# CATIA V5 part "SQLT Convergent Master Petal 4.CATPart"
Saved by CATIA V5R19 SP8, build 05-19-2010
Part number: SQLT Convergent Master Petal 4
Publications: "Droite.1", "Plan.1", "Plan.2", "Droite.2", "Droite.3", "Plan.3", "Droite.4", "Plan.4", "Plan.5", "Droite.5", "Plan.6", "Plan.7", "Point.4", "Point.5"
Bounding box of the stored display mesh (mm): x -150 to 150, y 530 to 730, z 400 to 600
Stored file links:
  G:\EU_thinkMotion\CFAO_2010\MMS_groupe3\MMS_groupe3\A reprendre\fovide\fovide\SQLT Convergent Master Petal 4.CATPart
  G:\EU_thinkMotion\CFAO_2010\MMS_groupe3\MMS_groupe3\A reprendre\fovide\fovide\fovide.CATProduct
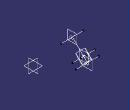
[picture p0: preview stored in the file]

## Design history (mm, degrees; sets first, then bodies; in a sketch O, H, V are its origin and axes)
Set1
  Point1 "Point.H": linked copy from another document
  Point2 "Point.I": linked copy from another document
  Point3 "Point.J": linked copy from another document
Set2 "se Convergent Master Petal"
  Line1: type PtPt, FirstPoint Point1, SecondPoint Point2
  Plane1: type OffsetPt, RefPlane yz-plane, RefPoint Point1
  Plane2: type OffsetPt, RefPlane yz-plane, RefPoint Point2
  Line2: type Normal, RefPoint Point2, RefSkin Plane2, Start -150, End 150
  Line3: type Normal, RefPoint Point1, RefSkin Plane1, Start -150, End 150
  Plane3: type OffsetPt, RefPlane Plane1, RefPoint Point3
  Line4: type Normal, RefPoint Point3, RefSkin Plane3, Start -150, End 150
  Plane4: type Normal, Curve Line1, RefPoint Point2
  Plane5: type Angle, RefPlane Plane4, Direction Line4, Angle 90
  Line5: type Normal, RefPoint Point3, RefSkin Plane5, Start -50, End 50
  Plane6: type Offset, RefPlane Plane5, Offset 3, reversed
  Plane7: type Offset, RefPlane Plane5, Offset 3
  Point4: type OnCurve, Support Line3, Length 130
  Point5: type OnCurve, Support Line2, Length 130
Body1 (main body)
